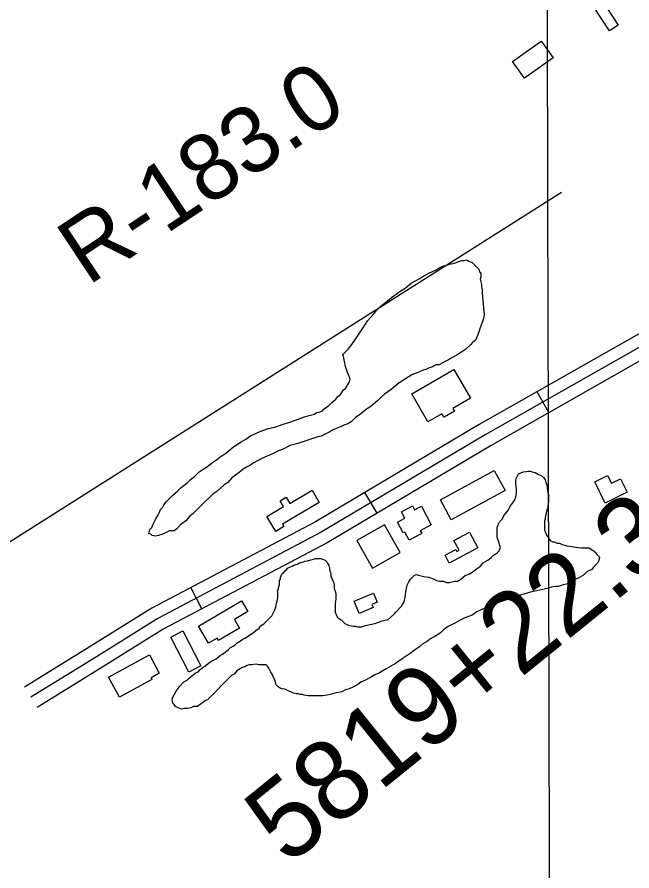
# Model space of a CAD drawing. Extents: x 3355724 to 3393621, y 594744 to 620174.
# Drawn here: x 3380230 to 3381002, y 607154 to 608225 of the extents above; entities that cross this region are included whole.
import ezdxf

# ---------------------------------------------------------------- set-up
doc = ezdxf.new("R2010")
doc.units = 0
for name, color, linetype in [('V-BLDG-OTLN', 7, 'Continuous'), ('V-GRID-MAJR', 7, 'Continuous'), ('V-RIVR-EDGE', 7, 'Continuous'), ('V-RIVR-RANG-IDEN', 7, 'Continuous'), ('V-ROAD-CNTR', 7, 'Continuous'), ('V-SITE-VEGE', 7, 'Continuous'), ('V-SURV-IDEN', 7, 'Continuous'), ('V-TOPO-SHOR', 7, 'Continuous')]:
    doc.layers.add(name, color=color, linetype=linetype)

msp = doc.modelspace()

# ---------------------------------------------------------------- linework, layer by layer
at = {"layer": 'V-BLDG-OTLN'}
for points in [[(3380973.8, 608207.6), (3380943.2, 608254.4), (3380960.8, 608265.9), (3380969.8, 608252), (3380963.2, 608247.7), (3380984.7, 608214.8)], [(3380902.9, 608173.8), (3380867, 608148.1), (3380852, 608169), (3380888, 608194.7)], [(3380725.6, 607752), (3380778.5, 607782.6), (3380799.3, 607746.7), (3380777, 607733.8), (3380779.1, 607730.2), (3380766.1, 607722.7), (3380763.5, 607727.2), (3380745.9, 607717)], [(3380842.6, 607631), (3380775.1, 607594.2), (3380761.6, 607619.1), (3380829.1, 607655.8)], [(3380995.8, 607628.6), (3380968.5, 607615.1), (3380955.3, 607641.9), (3380971.3, 607649.8), (3380976.1, 607640.1), (3380987.4, 607645.6)], [(3380609.5, 607615.7), (3380563.4, 607588.5), (3380565.1, 607585.5), (3380555, 607579.5), (3380543.8, 607598.4), (3380564.6, 607610.6), (3380560.4, 607617.8), (3380568, 607622.3), (3380572.5, 607614.7), (3380600.4, 607631.2)], [(3380750, 607587.8), (3380736.2, 607580.4), (3380738.1, 607577), (3380722.2, 607568.5), (3380716.8, 607578.7), (3380714.8, 607577.6), (3380707.6, 607591), (3380717, 607596), (3380712.7, 607604.1), (3380726.4, 607611.5), (3380729, 607606.5), (3380737.6, 607611.1)], [(3380691.3, 607587.8), (3380656.6, 607567.9), (3380676.5, 607533.2), (3380711.2, 607553.1)], [(3380798, 607578.6), (3380808.6, 607558.7), (3380772.6, 607539.6), (3380767.3, 607549.6), (3380780.9, 607556.8), (3380782.1, 607554.5), (3380785, 607556), (3380778.5, 607568.2)], [(3380653.2, 607492.1), (3380677.5, 607502.2), (3380682.3, 607490.6), (3380675.4, 607487.8), (3380677, 607484), (3380659.7, 607476.7)], [(3380458.1, 607460.6), (3380512, 607492.3), (3380519.9, 607479), (3380503, 607469), (3380509.3, 607458.2), (3380483, 607442.7), (3380481.3, 607445.5), (3380470.6, 607439.3)], [(3380445.8, 607403), (3380423, 607446.7), (3380438.1, 607454.6), (3380460.9, 607410.9)], [(3380345.1, 607396.7), (3380396.3, 607424.6), (3380408.7, 607401.7), (3380398.3, 607396), (3380399.4, 607393.9), (3380358.7, 607371.7)]]:
    msp.add_lwpolyline(points, close=True, dxfattribs=at)
at = {"layer": 'V-GRID-MAJR'}
msp.add_spline([(3380917.6, 600183.6), (3380900.8, 606241.7), (3380884.1, 612302.9), (3380867.3, 618364.1), (3380867.3, 618367.2)], degree=3, dxfattribs=at)
at = {"layer": 'V-RIVR-EDGE'}
msp.add_spline([(3375380.8, 618352.8), (3375420.3, 618323.7), (3375445.1, 618301.4), (3375471.3, 618279.7), (3375501.3, 618255.2), (3375536.3, 618227.7), (3375549, 618211.9), (3375560, 618204.9), (3375576.4, 618194.3), (3375599.8, 618175.2), (3375638.8, 618140.8), (3375656.3, 618122.5), (3375673.4, 618104.9), (3375771.5, 618011.4), (3375800.3, 617985.8), (3375821.8, 617963.4), (3375844.1, 617941), (3375861.6, 617929.7), (3375882.4, 617909.5), (3375904.3, 617880.2), (3375960.4, 617832.6), (3375992.2, 617799.6), (3376041, 617748.3), (3376074.6, 617712), (3376185.4, 617603.2), (3376227, 617561.8), (3376338.6, 617455.8), (3376382, 617411.9), (3376437.4, 617359.1), (3376479.7, 617314.8), (3376500.1, 617289.5), (3376531.5, 617258), (3376571.6, 617217.3), (3376620, 617160.1), (3376637.9, 617137.1), (3376661.2, 617115.1), (3376679.5, 617099), (3376697.7, 617079.5), (3376717, 617058.3), (3376731.6, 617036.7), (3376745.5, 617023.1), (3376758.9, 617009.2), (3376794.7, 616969.6), (3376867.2, 616883.2), (3376881.8, 616866.7), (3376901.8, 616844), (3376931.4, 616817.2), (3376968.6, 616773.3), (3377038.2, 616690.1), (3377067, 616652.8), (3377087.7, 616633), (3377103.1, 616618.7), (3377120.9, 616596.3), (3377186.5, 616512.5), (3377216, 616475.5), (3377255.4, 616427.8), (3377303.9, 616366.3), (3377369.5, 616288.3), (3377405.9, 616245.8), (3377491.5, 616128.6), (3377526.1, 616075.9), (3377552.7, 616041.1), (3377626.7, 615950.2), (3377654.4, 615916.2), (3377678.5, 615886.1), (3377699.9, 615857.2), (3377777.9, 615752.5), (3377803.1, 615722.8), (3377843.5, 615678.1), (3377868, 615650.3), (3377881.4, 615632), (3377905.5, 615598.3), (3377926.6, 615565.7), (3377940.8, 615543.3), (3377958.6, 615518.8), (3377971.8, 615499.4), (3377982.7, 615481.5), (3378059.6, 615375.3), (3378094.5, 615325.1), (3378126.9, 615277.1), (3378185.2, 615175.7), (3378207, 615135.1), (3378307.9, 614987.2), (3378349.4, 614923.1), (3378390.9, 614864.1), (3378419.7, 614826.4), (3378449.2, 614789.4), (3378467.1, 614756.1), (3378482.3, 614726.5), (3378509.6, 614679.2), (3378546.1, 614621), (3378577.4, 614566.5), (3378597.7, 614524.8), (3378622.5, 614473.9), (3378650.1, 614424.5), (3378694.9, 614351.3), (3378714.9, 614311), (3378749.1, 614248), (3378759.7, 614232.7), (3378776.8, 614205.9), (3378791.7, 614173), (3378807.7, 614137.9), (3378844.8, 614066.9), (3378863.7, 614025.1), (3378885.9, 613990.7), (3378900.1, 613964), (3378916.5, 613936.5), (3378929.2, 613918.2), (3379005.7, 613794.9), (3379023.2, 613762.6), (3379029, 613751.7), (3379038.1, 613737.7), (3379056, 613722), (3379063.3, 613712.5), (3379072.7, 613690.1), (3379096.7, 613633.4), (3379107.6, 613608.2), (3379127.6, 613568.3), (3379150.2, 613527.3), (3379171.3, 613493.2), (3379216, 613409.4), (3379256.8, 613334.4), (3379315, 613211.4), (3379346.2, 613141.1), (3379363.7, 613098.3), (3379415.7, 613001.7), (3379435.3, 612957.8), (3379449.5, 612923.7), (3379470.6, 612881.7), (3379540.5, 612751), (3379564.9, 612706.3), (3379589.6, 612660.6), (3379652.2, 612553.7), (3379662.4, 612531), (3379662.7, 612523.7), (3379672.9, 612508.3), (3379687.9, 612480.8), (3379704.2, 612446.8), (3379704.9, 612442.1), (3379706, 612437.3), (3379717.7, 612409.1), (3379731.5, 612386.4), (3379735.1, 612376.9), (3379746, 612355), (3379762.1, 612334.4), (3379789.4, 612292), (3379802.8, 612266.3), (3379844, 612191.3), (3379872.7, 612135.7), (3379896.4, 612098.3), (3379901.5, 612083), (3379906.5, 612054.8), (3379909.4, 612046.8), (3379918.9, 612032.8), (3379935.3, 612013.1), (3379944.7, 611991.5), (3379953.4, 611964), (3379958.9, 611953.4), (3379967.3, 611946.1), (3379978.6, 611926.7), (3379993.5, 611900), (3380009.5, 611874.3), (3380070.3, 611759.4), (3380080.8, 611731.2), (3380088.1, 611713.3), (3380095.7, 611697.6), (3380112.5, 611674.1), (3380124.8, 611651.8), (3380123.7, 611645.2), (3380124.8, 611635.3), (3380137.2, 611610.5), (3380148.8, 611592.5), (3380155, 611587.8), (3380167, 611570.5), (3380177.6, 611546.4), (3380195.8, 611514.2), (3380214.7, 611483.4), (3380224.5, 611465.9), (3380228.1, 611449.4), (3380233.6, 611432.6), (3380254, 611396), (3380276.5, 611349.1), (3380294, 611306.3), (3380320.9, 611258.7), (3380341.3, 611224.7), (3380352.6, 611207.5), (3380364.6, 611196.1), (3380367.1, 611187.7), (3380368.9, 611179.6), (3380378.4, 611166.5), (3380389, 611155.5), (3380389, 611150), (3380391.1, 611136.8), (3380399.1, 611120.7), (3380419.9, 611089.6), (3380436.7, 611073.5), (3380444.3, 611062.8), (3380444, 611058.8), (3380442.8, 611053), (3380446.5, 611044.9), (3380460, 611025.9), (3380464.3, 611010.9), (3380471.2, 610992.2), (3380486.5, 610958.2), (3380519.3, 610912.8), (3380526.9, 610891.2), (3380537.4, 610858.3), (3380551.6, 610822.8), (3380593.8, 610740.1), (3380615.2, 610699.4), (3380640.7, 610663.5), (3380652.4, 610642.3), (3380663.6, 610615.2), (3380668, 610601.3), (3380674.2, 610590.7), (3380692.1, 610574.9), (3380702.6, 610562.5), (3380712.5, 610543.8), (3380727.7, 610509.8), (3380735.3, 610487.8), (3380741.1, 610466.3), (3380745.9, 610461.1), (3380752.8, 610456.4), (3380760.5, 610445.7), (3380779.7, 610409.1), (3380795.8, 610376.2), (3380801.6, 610370.3), (3380807.4, 610366.3), (3380811.8, 610355.7), (3380812.5, 610344.4), (3380817.9, 610330.5), (3380829.2, 610313.2), (3380839, 610293.8), (3380846.3, 610289.4), (3380854, 610282.8), (3380859.1, 610273.7), (3380867.1, 610253.9), (3380868.5, 610249.5), (3380877.7, 610239.6), (3380887.1, 610223.9), (3380896.6, 610208.5), (3380899.8, 610194.3), (3380899.8, 610190.2), (3380906, 610188.8), (3380913, 610185.1), (3380918.4, 610177), (3380918.4, 610171.2), (3380918.4, 610164.6), (3380918.4, 610157.7), (3380926.1, 610151.8), (3380935.5, 610140.8), (3380947.2, 610118.8), (3380956.3, 610103.8), (3380965, 610094.7), (3380973.4, 610078.9), (3380975.2, 610070.2), (3380981.8, 610062.1), (3380992.7, 610052.9), (3380996.7, 610044.9), (3381000, 610032.1), (3381000, 610022.9), (3381003.2, 610013.1), (3381010.1, 610006.8), (3381018.9, 610001.3), (3381025.8, 609991.4), (3381035.3, 609976.8), (3381052, 609952.3), (3381064.1, 609932.5), (3381081.2, 609901.7), (3381081.1, 609891.9), (3381086.6, 609872.9), (3381093.8, 609850.9), (3381104, 609830.4), (3381125.5, 609791.6), (3381152.4, 609750.2), (3381171, 609723.9), (3381189.6, 609688), (3381212.1, 609645.9), (3381231.4, 609613.3), (3381244.1, 609581.5), (3381257.9, 609543.1), (3381275, 609509.4), (3381303.1, 609460.3), (3381339.8, 609389.7), (3381375.9, 609334), (3381398.4, 609297.8), (3381410.8, 609276.6), (3381420.3, 609271.8), (3381423.2, 609268.1), (3381426.1, 609261.5), (3381429.8, 609259.3), (3381434.9, 609258.6), (3381439.6, 609256.4), (3381499.3, 609155.7), (3381528.1, 609097.9), (3381535.4, 609085.1), (3381535.3, 609077), (3381535.3, 609065.3), (3381535.3, 609058), (3381541.1, 609053.6), (3381551.7, 609048.5), (3381555, 609039.7), (3381564.1, 609020.7), (3381586.3, 608978.9), (3381604.8, 608944.2), (3381620.1, 608915.3), (3381628.5, 608903.5), (3381636.9, 608898.4), (3381651.1, 608874.6), (3381663.1, 608850.8), (3381678.4, 608829.2), (3381690.8, 608814.6), (3381704.6, 608790.4), (3381708.2, 608774.7), (3381710.4, 608757.8), (3381710.4, 608748.7), (3381708.5, 608737.7), (3381708.1, 608732.3), (3381711.4, 608718), (3381715.7, 608697.2), (3381717.9, 608689.8), (3381723.3, 608678.5), (3381733.5, 608661.7), (3381741.6, 608656.5), (3381747, 608652.5), (3381752.9, 608648.1), (3381759.8, 608648.1), (3381763.5, 608647), (3381765.6, 608640.7), (3381769.3, 608633.4), (3381776.2, 608626.5), (3381784.6, 608625), (3381791.6, 608623.9), (3381802.1, 608612.9), (3381808.3, 608607.4), (3381820.7, 608590.9), (3381831.7, 608582.8), (3381840.8, 608572.6), (3381857.5, 608537.8), (3381870.2, 608504.1), (3381876, 608481.4), (3381884.7, 608465), (3381898.6, 608444.1), (3381913.5, 608430.2), (3381932.1, 608392.5), (3381960.8, 608337.2), (3381973.6, 608310.9), (3381973.6, 608307.2), (3381972.8, 608299.9), (3381972.8, 608295.1), (3381975, 608287.8), (3381977.9, 608282.3), (3381985.9, 608277.2), (3381990.3, 608271), (3381997.2, 608259.3), (3382005.9, 608242.4), (3382015.7, 608221.2), (3382031, 608193), (3382044.5, 608168.9), (3382063, 608134.1), (3382080.1, 608094.9), (3382096.5, 608059.1), (3382116.9, 608016.6), (3382135.1, 607983.3), (3382154.3, 607945.2), (3382180.5, 607890), (3382186.3, 607875.7), (3382201.6, 607836.9), (3382211, 607801.1), (3382219, 607778), (3382226.3, 607767), (3382233.6, 607756.8), (3382247.7, 607722.7), (3382259, 607698.2), (3382261.5, 607688.4), (3382266.6, 607674.8), (3382271, 607670.4), (3382277.9, 607659.4), (3382286.3, 607646.3), (3382288.8, 607636.7), (3382293.5, 607621), (3382300.4, 607600.9), (3382310.6, 607578.9), (3382319.7, 607565.7), (3382337.9, 607536.8), (3382350.3, 607516.3), (3382357.6, 607499.1), (3382366.3, 607481.9), (3382374.3, 607469.5), (3382380.9, 607464), (3382386.7, 607463.2), (3382390.7, 607463.2), (3382394.4, 607459.9), (3382404.9, 607439.1), (3382412.6, 607420), (3382419.1, 607395.5), (3382431.8, 607365.5), (3382444.5, 607337), (3382461.3, 607305.9), (3382481.6, 607263.8), (3382528.3, 607190.2), (3382546.8, 607161.6), (3382558.1, 607140), (3382565.4, 607121.4), (3382577.7, 607099), (3382593.8, 607069.8), (3382609.4, 607044.1), (3382624.3, 607021.4), (3382632.4, 607011.2), (3382645.5, 606998), (3382659.3, 606987), (3382671.4, 606972.7), (3382685.2, 606951.8)], degree=3, dxfattribs=at)
at = {"layer": 'V-ROAD-CNTR'}
for p, q in [((3380897.7, 607728.7), (3380882.9, 607754.7)), ((3380682.1, 607602.6), (3380666.8, 607628.4)), ((3380462.1, 607482.5), (3380448.1, 607509.1))]:
    msp.add_line(p, q, dxfattribs=at)
for points in [[(3381362.1, 608024.9), (3381113.3, 607885.7), (3380810.3, 607713.5), (3380604.6, 607591.5), (3380399.3, 607483.4), (3380315.1, 607430.8), (3380239.7, 607384.2)], [(3381369.4, 608011.8), (3381120.7, 607872.7), (3380817.9, 607700.5), (3380612, 607578.4), (3380406.8, 607470.4), (3380323, 607418.1), (3380247.5, 607371.5)], [(3381376.7, 607998.7), (3381128, 607859.6), (3380825.4, 607687.5), (3380619.3, 607565.3), (3380414.2, 607457.4), (3380331, 607405.3), (3380255.4, 607358.7)]]:
    msp.add_lwpolyline(points, dxfattribs=at)
at = {"layer": 'V-SITE-VEGE'}
for points in [[(3380531.4, 607703), (3380537.3, 607705.6), (3380544, 607708.1), (3380554.8, 607710.7), (3380564.1, 607714.1), (3380572.4, 607716.6), (3380584.1, 607720.9), (3380590.8, 607723.4), (3380596.7, 607725.1), (3380603.4, 607726.8), (3380605.9, 607728.5), (3380609.2, 607729.3), (3380613.4, 607731), (3380615.1, 607732.7), (3380621.8, 607737.8), (3380625.1, 607741.1), (3380630.1, 607745.4), (3380632.6, 607748.7), (3380636, 607751.3), (3380640.1, 607757.1), (3380642.6, 607758.8), (3380647.6, 607767.2), (3380648.4, 607770.6), (3380647.6, 607773.1), (3380645.1, 607778.9), (3380642.5, 607786.5), (3380639.9, 607799), (3380639.1, 607801.5), (3380645.8, 607808.3), (3380649.1, 607812.5), (3380653.3, 607818.4), (3380660.8, 607829.3), (3380665.8, 607836.9), (3380669.9, 607843.6), (3380677.4, 607852), (3380681.6, 607857), (3380686.6, 607862.1), (3380695, 607868.8), (3380700, 607873), (3380710.8, 607880.6), (3380717.5, 607884.9), (3380725, 607890.8), (3380735.9, 607896.7), (3380740.9, 607900), (3380746.8, 607903.4), (3380756, 607907.6), (3380760.1, 607910.2), (3380766, 607912.7), (3380775.2, 607915.3), (3380779.4, 607916.1), (3380783.6, 607917.8), (3380788.6, 607919.5), (3380791.1, 607919.5), (3380794.5, 607920.4), (3380797, 607918.7), (3380801.2, 607917.1), (3380809.6, 607908.7), (3380810.4, 607905.4), (3380812.1, 607902.9), (3380812.1, 607898.7), (3380811.3, 607896.2), (3380813, 607889.5), (3380813, 607886.1), (3380813.9, 607882.8), (3380813.9, 607878.6), (3380816.5, 607850.9)], [(3380816.5, 607850.9), (3380815.7, 607846.7), (3380814.1, 607841.7), (3380811.6, 607835), (3380809.1, 607827.4), (3380807.4, 607823.2), (3380805.8, 607819.9), (3380801.6, 607816.5), (3380799.9, 607814), (3380793.3, 607808.1), (3380783.2, 607801.3), (3380775.7, 607797.1), (3380771.5, 607794.6), (3380767.4, 607792.9), (3380759.8, 607788.7), (3380755.6, 607788.6), (3380751.5, 607786.1), (3380746.4, 607784.4), (3380743.1, 607782.7), (3380739.7, 607781.9), (3380732.2, 607778.5), (3380725.5, 607775.9), (3380709.6, 607765.8), (3380699.6, 607757.4), (3380691.3, 607751.5), (3380687.1, 607748.1), (3380682.9, 607743.9), (3380677.1, 607738.9), (3380672.9, 607735.5), (3380668.7, 607733), (3380659.5, 607725.4), (3380655.4, 607722.8), (3380649.5, 607717), (3380645.3, 607714.4), (3380640.3, 607712.7), (3380637, 607711), (3380628.6, 607707.6), (3380625.3, 607706), (3380622.8, 607704.3), (3380616.9, 607701.7), (3380611.9, 607699.2), (3380607.7, 607698.3), (3380582.6, 607689.8), (3380572.5, 607687.3), (3380565, 607683.1), (3380558.3, 607680.5), (3380550, 607676.3), (3380538.3, 607671.2), (3380526.6, 607665.3), (3380523.2, 607662.8), (3380518.2, 607660.2), (3380514, 607657.7), (3380509, 607653.5), (3380499.8, 607646.7), (3380494.8, 607640.9), (3380489.8, 607637.5), (3380481.5, 607629.9), (3380476.4, 607626.5), (3380472.3, 607622.3), (3380465.6, 607616.4), (3380451.4, 607602.1), (3380447.2, 607598.8), (3380442.2, 607592.9), (3380435.5, 607587.8), (3380430.5, 607582.8), (3380427.2, 607580.2), (3380421.3, 607580.2), (3380413, 607576), (3380407.9, 607574.3), (3380403.8, 607573.4), (3380399.6, 607574.2), (3380397.9, 607575.9), (3380395.4, 607576.7), (3380397, 607581.8), (3380399.5, 607584.3), (3380401.2, 607588.5), (3380404.5, 607595.2), (3380407, 607599.4), (3380408.7, 607602.8), (3380410.3, 607607), (3380412.8, 607609.5), (3380414.5, 607612.9), (3380417.8, 607617.1), (3380425.3, 607624.6), (3380432, 607630.5), (3380436.2, 607634.7), (3380443.7, 607640.6), (3380447.9, 607644.8), (3380452.9, 607648.2), (3380458.7, 607654.1), (3380463.7, 607657.5), (3380467.9, 607660), (3380475.4, 607665.9), (3380480.4, 607669.3), (3380484.6, 607672.7), (3380492.1, 607677.7), (3380502.2, 607686.1), (3380511.4, 607692), (3380517.2, 607695.4), (3380523.1, 607699.6), (3380531.4, 607703)], [(3380602.1, 607544.7), (3380604.8, 607545.4), (3380611.5, 607545.4), (3380613.5, 607544.7), (3380616.8, 607543.4), (3380618.8, 607541.4), (3380620.2, 607538.8), (3380621.5, 607536.8), (3380622.2, 607533.4), (3380622.2, 607531.4), (3380623.6, 607528.1), (3380624.2, 607525.4), (3380624.2, 607523.4), (3380625.6, 607519.5), (3380626.9, 607516.8), (3380627.6, 607514.8), (3380628.3, 607511.5), (3380628.3, 607508.1), (3380629, 607505.5), (3380629.7, 607503.5), (3380630.3, 607500.1), (3380630.4, 607494.8), (3380629.6, 607488.9), (3380629.6, 607478), (3380632.1, 607472.2), (3380634.7, 607469.7), (3380637.2, 607468), (3380641.4, 607463.8), (3380644.8, 607462.2), (3380651.5, 607460.5), (3380654.8, 607460.5), (3380657.3, 607459.7), (3380662.4, 607459.7), (3380667.4, 607461.4), (3380679.1, 607464), (3380684.1, 607465.7), (3380688.3, 607467.4), (3380695.8, 607469.1), (3380703.4, 607475.8), (3380705.9, 607478.4), (3380712.5, 607485.9), (3380715.9, 607491), (3380717.5, 607496.8), (3380718.3, 607503.6), (3380720, 607511.9), (3380721.6, 607515.3), (3380724.1, 607519.5), (3380729.1, 607524.6), (3380731.6, 607525.4), (3380734.2, 607524.6), (3380740.9, 607522.9), (3380746.7, 607522.1), (3380753.5, 607519.6), (3380756.8, 607518), (3380760.2, 607517.1), (3380765.2, 607517.2), (3380768.6, 607515.5), (3380772.7, 607515.5), (3380779.4, 607517.2), (3380782.8, 607517.2), (3380787, 607519.8), (3380792.8, 607524), (3380797, 607525.7), (3380801.2, 607528.2), (3380807, 607532.4), (3380812, 607535.8), (3380815.4, 607540), (3380821.2, 607543.4), (3380825.4, 607546.8), (3380827.9, 607549.3), (3380832.9, 607552.7), (3380835.4, 607555.2), (3380837.1, 607559.4), (3380836.2, 607561.9), (3380835.4, 607565.2), (3380832.8, 607571.9), (3380832.8, 607584.5), (3380833.6, 607587), (3380836.1, 607592.1), (3380839.4, 607595.4), (3380841.1, 607599.6), (3380846.1, 607605.5), (3380849.4, 607611.4), (3380854.4, 607618.1), (3380856.1, 607623.1), (3380856.9, 607627.3), (3380856.9, 607633.2), (3380856, 607639.1), (3380856, 607643.3), (3380856.8, 607645.8), (3380858.5, 607650), (3380860.1, 607651.7), (3380863.5, 607653.4), (3380866, 607654.2), (3380871.9, 607655.1), (3380874.4, 607655.1), (3380876.9, 607654.2), (3380880.3, 607653.4), (3380884.5, 607650.9), (3380888.7, 607649.3)], [(3380888.7, 607649.3), (3380891.2, 607646.8), (3380892.9, 607644.3), (3380893.7, 607640.9), (3380895.4, 607636.7), (3380895.4, 607634.2), (3380896.3, 607628.4), (3380897.1, 607625.8), (3380897.2, 607616.6), (3380896.4, 607611.6), (3380896.4, 607609.1), (3380894.7, 607604.9), (3380892.2, 607592.3), (3380892.3, 607580.6), (3380894, 607577.2), (3380894.8, 607574.7), (3380897.4, 607571.4), (3380899.1, 607568), (3380902.4, 607566.4), (3380904.9, 607566.4), (3380907.5, 607564.7), (3380910.8, 607564.7), (3380914.2, 607563.1), (3380917.5, 607562.2), (3380920, 607561.4), (3380937.6, 607559), (3380947.7, 607559), (3380951.9, 607556.5), (3380954.4, 607554.9), (3380956.1, 607553.2), (3380957.8, 607550.7), (3380961.2, 607547.3), (3380960.3, 607543.2), (3380958.7, 607539.8), (3380953.7, 607534.7), (3380951.2, 607531.4), (3380948.7, 607530.5), (3380945.3, 607528.8), (3380941.1, 607524.6), (3380935.3, 607521.3), (3380929.4, 607518.7), (3380921.1, 607513.6), (3380914.4, 607511.9), (3380909.4, 607510.2), (3380906, 607510.2), (3380901, 607509.4), (3380895.1, 607507.7), (3380890.1, 607506.8), (3380882.6, 607505.1), (3380877.5, 607504.2), (3380863.3, 607500), (3380858.3, 607498.3), (3380854.1, 607496.6), (3380845.7, 607494.1), (3380835.7, 607490.7), (3380829, 607488.1), (3380817.3, 607483), (3380807.3, 607478.8), (3380801.4, 607474.6), (3380792.2, 607471.2), (3380785.5, 607467.8), (3380779.7, 607464.4), (3380771.3, 607460.2), (3380765.5, 607456), (3380761.3, 607451.8), (3380754.6, 607447.6), (3380749.6, 607445), (3380745.4, 607441.7), (3380739.6, 607438.3), (3380735.4, 607434.9), (3380730.4, 607431.5), (3380723.7, 607426.5), (3380713.7, 607419.7), (3380705.3, 607413.8), (3380693.6, 607407.1), (3380685.2, 607402), (3380679.4, 607399.5), (3380675.2, 607396.9), (3380667.7, 607392.7), (3380661.8, 607390.2), (3380657.7, 607387.6), (3380650.1, 607383.4), (3380645.9, 607381.7), (3380642.6, 607380.9), (3380637.6, 607378.3), (3380629.2, 607376.6), (3380623.3, 607374.9), (3380619.2, 607374.1), (3380614.1, 607373.2), (3380595.7, 607373.1), (3380590.7, 607373.9), (3380588.1, 607374.8), (3380585.6, 607374.8), (3380583.1, 607375.6), (3380580.6, 607375.6), (3380577.2, 607376.4), (3380573.9, 607378.1), (3380571.4, 607378.9), (3380566.3, 607381.4), (3380563, 607382.2), (3380560.5, 607383)], [(3380560.5, 607383), (3380557.9, 607384.7), (3380555.4, 607387.2), (3380554.6, 607390.5), (3380553.7, 607393.1), (3380552, 607396.4), (3380550.3, 607400.6), (3380548.6, 607403.1), (3380546.1, 607408.1), (3380544.4, 607410.6), (3380542.7, 607412.3), (3380533.5, 607412.2), (3380530.2, 607413.1), (3380524.3, 607412.2), (3380521.8, 607412.2), (3380518.4, 607411.3), (3380515.9, 607409.7), (3380512.6, 607408.8), (3380510.1, 607407.1), (3380505.9, 607404.6), (3380502.6, 607400.4), (3380499.2, 607398.7), (3380469.2, 607368.4), (3380466.7, 607367.5), (3380462.5, 607364.2), (3380460, 607362.5), (3380456.6, 607360), (3380451.6, 607359.9), (3380448.3, 607358.2), (3380444.1, 607357.4), (3380439.9, 607357.4), (3380436.5, 607356.5), (3380432.3, 607358.2), (3380429, 607359.8), (3380427.3, 607362.3), (3380425.6, 607364), (3380424.8, 607369), (3380425.6, 607371.6), (3380429.7, 607379.1), (3380432.2, 607382.5), (3380433.9, 607385), (3380439.7, 607390.9), (3380443.9, 607393.4), (3380445.6, 607395.1), (3380448.9, 607397.6), (3380453.9, 607401.8), (3380457.3, 607403.5), (3380459.8, 607406.1), (3380464, 607409.4), (3380466.5, 607410.3), (3380468.1, 607412), (3380473.2, 607416.2), (3380479.9, 607419.6), (3380484.9, 607423.8), (3380488.2, 607425.5), (3380491.5, 607428), (3380495.7, 607431.4), (3380498.2, 607433.9), (3380501.6, 607435.6), (3380504.1, 607437.3), (3380506.6, 607439.8), (3380510.8, 607442.3), (3380514.1, 607444.8), (3380516.6, 607445.7), (3380522.5, 607449.9), (3380526.6, 607452.4), (3380530, 607455), (3380534.2, 607458.3), (3380535.8, 607460.9), (3380540, 607463.4), (3380550, 607473.5), (3380554.2, 607481.9), (3380555, 607484.4), (3380555.8, 607489.4), (3380556.6, 607492), (3380557.5, 607496.2), (3380557.6, 607499.1), (3380557.6, 607505.8), (3380558.3, 607507.8), (3380558.9, 607510.5), (3380559.6, 607512.5), (3380559.6, 607517.8), (3380560.9, 607519.8), (3380560.9, 607521.8), (3380561.5, 607523.8), (3380562.9, 607526.5), (3380564.9, 607527.9), (3380566.2, 607529.9), (3380568.2, 607531.2), (3380569.5, 607533.2), (3380573.5, 607535.2), (3380575.5, 607535.9), (3380577.5, 607537.3), (3380580.1, 607537.9), (3380582.1, 607538.6), (3380584.1, 607540), (3380589.5, 607541.3), (3380591.5, 607542), (3380594.8, 607542.7), (3380598.8, 607544), (3380602.1, 607544.7)]]:
    msp.add_lwpolyline(points, dxfattribs=at)
at = {"layer": 'V-TOPO-SHOR'}
msp.add_line((3380913.4, 608004.9), (3379938, 607387), dxfattribs=at)

# ---------------------------------------------------------------- texts
at = {"layer": 'V-RIVR-RANG-IDEN'}
msp.add_text('R-183.0', height=83, rotation=33.5464, dxfattribs=at).set_placement((3380319, 607886.9))
at = {"layer": 'V-SURV-IDEN'}
msp.add_text('5819+22.3', height=100, rotation=38.9611, dxfattribs=at).set_placement((3380569.7, 607158.8))

doc.saveas('drawing.dxf')
